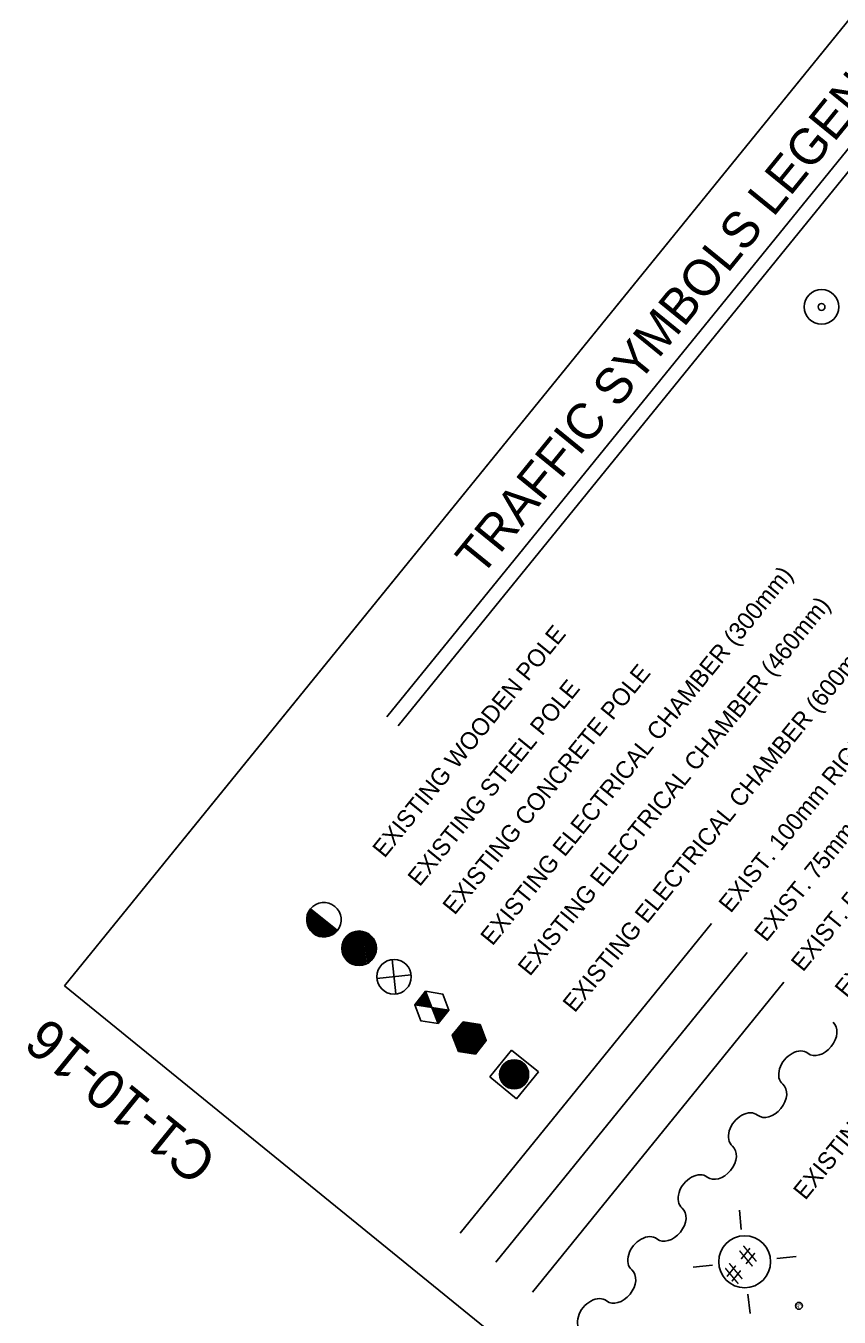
# Model space of a CAD drawing. Extents: x 592613 to 600223, y 4837996 to 4840103.
# Drawn here: x 592657.51 to 592677.9, y 4838962.54 to 4838994.9 of the extents above; entities that cross this region are included whole.
import ezdxf

# ---------------------------------------------------------------- set-up
doc = ezdxf.new("R2010")
doc.units = 0
for name, color, linetype in [('ENG_BORDER', 7, 'Continuous'), ('ENG_TX_BORDER', 7, 'Continuous'), ('TCS_100mm-EXIST', 7, 'Continuous'), ('TCS_50mm-EXIST', 7, 'Continuous'), ('TCS_75mm-EXIST', 7, 'Continuous'), ('TCS_ELEC-CHAMBER-EXIST', 7, 'Continuous'), ('TCS_LEGEND', 7, 'Continuous'), ('TCS_LUMINAIRE-EXIST', 7, 'Continuous'), ('TCS_POLE-EXIST', 7, 'Continuous'), ('TCS_POLE-NEW', 7, 'Continuous'), ('TCS_PUSHBUTTON', 7, 'Continuous'), ('TCS_SPAN-EXIST', 7, 'Continuous')]:
    doc.layers.add(name, color=color, linetype=linetype)

msp = doc.modelspace()

# ---------------------------------------------------------------- linework, layer by layer
at = {"layer": 'ENG_BORDER'}
for points in [[(592783.858, 4839125.156), (592658.479, 4838970.843)], [(592658.479, 4838970.843), (592762.862, 4838886.033)]]:
    msp.add_lwpolyline(points, dxfattribs=at)
at = {"layer": 'TCS_100mm-EXIST'}
msp.add_line((592668.401, 4838964.64), (592674.707, 4838972.401), dxfattribs=at)
at = {"layer": 'TCS_50mm-EXIST'}
msp.add_line((592670.214, 4838963.166), (592676.52, 4838970.928), dxfattribs=at)
at = {"layer": 'TCS_75mm-EXIST'}
msp.add_line((592669.292, 4838963.916), (592675.598, 4838971.677), dxfattribs=at)
at = {"layer": 'TCS_ELEC-CHAMBER-EXIST'}
for p, q in [((592667.302, 4838970.359), (592667.297, 4838970.408)), ((592667.316, 4838970.357), (592667.309, 4838970.424)), ((592667.331, 4838970.355), (592667.322, 4838970.44)), ((592667.346, 4838970.352), (592667.335, 4838970.456)), ((592667.361, 4838970.35), (592667.348, 4838970.472)), ((592667.375, 4838970.347), (592667.361, 4838970.488)), ((592667.39, 4838970.345), (592667.374, 4838970.504)), ((592667.405, 4838970.343), (592667.387, 4838970.519)), ((592667.42, 4838970.34), (592667.4, 4838970.535)), ((592667.435, 4838970.338), (592667.413, 4838970.551)), ((592667.449, 4838970.336), (592667.425, 4838970.567)), ((592667.464, 4838970.333), (592667.438, 4838970.583)), ((592667.479, 4838970.331), (592667.451, 4838970.599)), ((592667.494, 4838970.329), (592667.464, 4838970.615)), ((592667.509, 4838970.326), (592667.477, 4838970.63)), ((592667.523, 4838970.324), (592667.49, 4838970.646)), ((592667.538, 4838970.321), (592667.503, 4838970.662)), ((592667.553, 4838970.319), (592667.516, 4838970.678)), ((592667.568, 4838970.317), (592667.529, 4838970.694)), ((592667.582, 4838970.314), (592667.545, 4838970.677)), ((592667.597, 4838970.312), (592667.565, 4838970.625)), ((592667.612, 4838970.31), (592667.585, 4838970.573)), ((592667.627, 4838970.307), (592667.605, 4838970.521)), ((592667.642, 4838970.305), (592667.625, 4838970.469)), ((592667.656, 4838970.302), (592667.645, 4838970.416)), ((592667.272, 4838970.364), (592667.271, 4838970.377)), ((592667.287, 4838970.362), (592667.284, 4838970.392)), ((592667.671, 4838970.3), (592667.664, 4838970.364)), ((592667.686, 4838970.298), (592667.684, 4838970.312)), ((592667.708, 4838970.25), (592667.704, 4838970.295)), ((592667.728, 4838970.197), (592667.718, 4838970.293)), ((592667.748, 4838970.145), (592667.733, 4838970.29)), ((592667.768, 4838970.093), (592667.748, 4838970.288)), ((592667.788, 4838970.041), (592667.763, 4838970.285)), ((592667.808, 4838969.989), (592667.777, 4838970.283)), ((592667.828, 4838969.937), (592667.792, 4838970.281)), ((592667.847, 4838969.894), (592667.807, 4838970.278)), ((592667.86, 4838969.91), (592667.822, 4838970.276)), ((592667.873, 4838969.926), (592667.837, 4838970.274)), ((592667.885, 4838969.942), (592667.851, 4838970.271)), ((592667.898, 4838969.958), (592667.866, 4838970.269)), ((592667.911, 4838969.974), (592667.881, 4838970.267)), ((592667.924, 4838969.989), (592667.896, 4838970.264)), ((592667.937, 4838970.005), (592667.91, 4838970.262)), ((592667.95, 4838970.021), (592667.925, 4838970.259)), ((592667.963, 4838970.037), (592667.94, 4838970.257)), ((592667.976, 4838970.053), (592667.955, 4838970.255)), ((592667.989, 4838970.069), (592667.97, 4838970.252)), ((592668.001, 4838970.085), (592667.984, 4838970.25)), ((592668.014, 4838970.1), (592667.999, 4838970.248)), ((592668.027, 4838970.116), (592668.014, 4838970.245)), ((592668.04, 4838970.132), (592668.029, 4838970.243)), ((592668.053, 4838970.148), (592668.043, 4838970.241)), ((592668.066, 4838970.164), (592668.058, 4838970.238)), ((592668.079, 4838970.18), (592668.073, 4838970.236)), ((592668.092, 4838970.196), (592668.088, 4838970.233)), ((592668.105, 4838970.212), (592668.103, 4838970.231)), ((592668.117, 4838970.227), (592668.117, 4838970.229)), ((592668.2, 4838969.604), (592668.473, 4838969.94)), ((592668.473, 4838969.94), (592668.2, 4838969.604)), ((592668.473, 4838969.94), (592668.2, 4838969.604)), ((592668.473, 4838969.94), (592668.2, 4838969.604)), ((592668.397, 4838969.191), (592668.337, 4838969.773)), ((592668.412, 4838969.189), (592668.35, 4838969.788)), ((592668.427, 4838969.187), (592668.363, 4838969.804)), ((592668.442, 4838969.184), (592668.376, 4838969.82)), ((592668.456, 4838969.182), (592668.389, 4838969.836)), ((592668.471, 4838969.18), (592668.402, 4838969.852)), ((592668.486, 4838969.177), (592668.415, 4838969.868)), ((592668.501, 4838969.175), (592668.427, 4838969.884)), ((592668.516, 4838969.173), (592668.44, 4838969.9)), ((592668.53, 4838969.17), (592668.453, 4838969.915)), ((592668.545, 4838969.168), (592668.466, 4838969.931)), ((592668.473, 4838969.94), (592668.902, 4838969.872)), ((592668.902, 4838969.872), (592668.473, 4838969.94)), ((592668.902, 4838969.872), (592668.473, 4838969.94)), ((592668.902, 4838969.872), (592668.473, 4838969.94)), ((592668.56, 4838969.165), (592668.48, 4838969.939)), ((592668.575, 4838969.163), (592668.495, 4838969.937)), ((592668.589, 4838969.161), (592668.509, 4838969.934)), ((592668.604, 4838969.158), (592668.524, 4838969.932)), ((592668.619, 4838969.156), (592668.539, 4838969.93)), ((592668.634, 4838969.154), (592668.554, 4838969.927)), ((592668.649, 4838969.151), (592668.569, 4838969.925)), ((592668.663, 4838969.149), (592668.583, 4838969.923)), ((592668.678, 4838969.147), (592668.598, 4838969.92)), ((592668.693, 4838969.144), (592668.613, 4838969.918)), ((592668.708, 4838969.142), (592668.628, 4838969.915)), ((592668.722, 4838969.139), (592668.642, 4838969.913)), ((592668.737, 4838969.137), (592668.657, 4838969.911)), ((592668.752, 4838969.135), (592668.672, 4838969.908)), ((592668.767, 4838969.132), (592668.687, 4838969.906)), ((592668.782, 4838969.13), (592668.702, 4838969.904)), ((592668.795, 4838969.144), (592668.716, 4838969.901)), ((592668.808, 4838969.16), (592668.731, 4838969.899)), ((592668.82, 4838969.176), (592668.746, 4838969.897)), ((592668.833, 4838969.192), (592668.761, 4838969.894)), ((592668.846, 4838969.208), (592668.775, 4838969.892)), ((592668.859, 4838969.224), (592668.79, 4838969.889)), ((592668.872, 4838969.24), (592668.805, 4838969.887)), ((592668.885, 4838969.255), (592668.82, 4838969.885)), ((592668.898, 4838969.271), (592668.835, 4838969.882)), ((592668.911, 4838969.287), (592668.849, 4838969.88)), ((592668.924, 4838969.303), (592668.864, 4838969.878)), ((592668.936, 4838969.319), (592668.879, 4838969.875)), ((592668.949, 4838969.335), (592668.894, 4838969.873)), ((592668.902, 4838969.872), (592669.056, 4838969.466)), ((592669.056, 4838969.466), (592668.902, 4838969.872)), ((592669.056, 4838969.466), (592668.902, 4838969.872)), ((592669.056, 4838969.466), (592668.902, 4838969.872)), ((592668.962, 4838969.351), (592668.911, 4838969.847)), ((592668.975, 4838969.366), (592668.931, 4838969.795)), ((592668.2, 4838969.604), (592668.355, 4838969.198)), ((592668.2, 4838969.604), (592668.355, 4838969.198)), ((592668.2, 4838969.604), (592668.355, 4838969.198)), ((592668.2, 4838969.604), (592668.355, 4838969.198)), ((592668.213, 4838969.569), (592668.208, 4838969.614)), ((592668.233, 4838969.517), (592668.221, 4838969.63)), ((592668.253, 4838969.465), (592668.234, 4838969.646)), ((592668.273, 4838969.413), (592668.247, 4838969.662)), ((592668.293, 4838969.36), (592668.26, 4838969.677)), ((592668.313, 4838969.308), (592668.273, 4838969.693)), ((592668.333, 4838969.256), (592668.286, 4838969.709)), ((592668.352, 4838969.204), (592668.299, 4838969.725)), ((592668.368, 4838969.196), (592668.311, 4838969.741)), ((592668.383, 4838969.194), (592668.324, 4838969.757)), ((592668.783, 4838969.13), (592669.056, 4838969.466)), ((592668.783, 4838969.13), (592669.056, 4838969.466)), ((592668.783, 4838969.13), (592669.056, 4838969.466)), ((592668.783, 4838969.13), (592669.056, 4838969.466)), ((592668.988, 4838969.382), (592668.951, 4838969.743)), ((592669.001, 4838969.398), (592668.971, 4838969.691)), ((592669.014, 4838969.414), (592668.991, 4838969.638)), ((592669.027, 4838969.43), (592669.011, 4838969.586)), ((592669.04, 4838969.446), (592669.031, 4838969.534)), ((592669.053, 4838969.462), (592669.05, 4838969.482)), ((592668.355, 4838969.198), (592668.783, 4838969.13)), ((592668.355, 4838969.198), (592668.783, 4838969.13)), ((592668.355, 4838969.198), (592668.783, 4838969.13)), ((592668.355, 4838969.198), (592668.783, 4838969.13)), ((592669.143, 4838968.557), (592669.69, 4838969.231)), ((592669.69, 4838969.231), (592670.364, 4838968.684)), ((592669.475, 4838968.386), (592669.433, 4838968.793)), ((592669.483, 4838968.377), (592669.439, 4838968.804)), ((592669.492, 4838968.368), (592669.445, 4838968.814)), ((592669.5, 4838968.36), (592669.452, 4838968.824)), ((592669.508, 4838968.352), (592669.458, 4838968.833)), ((592669.516, 4838968.345), (592669.464, 4838968.842)), ((592669.524, 4838968.338), (592669.471, 4838968.85)), ((592669.532, 4838968.332), (592669.477, 4838968.857)), ((592669.539, 4838968.326), (592669.484, 4838968.865)), ((592669.547, 4838968.321), (592669.49, 4838968.872)), ((592669.555, 4838968.315), (592669.497, 4838968.879)), ((592669.563, 4838968.31), (592669.503, 4838968.885)), ((592669.571, 4838968.306), (592669.51, 4838968.891)), ((592669.578, 4838968.301), (592669.517, 4838968.897)), ((592669.586, 4838968.297), (592669.523, 4838968.903)), ((592669.594, 4838968.293), (592669.53, 4838968.908)), ((592669.601, 4838968.29), (592669.537, 4838968.913)), ((592669.609, 4838968.286), (592669.544, 4838968.918)), ((592669.617, 4838968.283), (592669.55, 4838968.923)), ((592669.624, 4838968.28), (592669.557, 4838968.927)), ((592669.632, 4838968.277), (592669.564, 4838968.931)), ((592669.639, 4838968.275), (592669.571, 4838968.935)), ((592669.647, 4838968.272), (592669.578, 4838968.939)), ((592669.654, 4838968.27), (592669.585, 4838968.943)), ((592669.662, 4838968.268), (592669.592, 4838968.947)), ((592669.669, 4838968.266), (592669.598, 4838968.95)), ((592669.677, 4838968.265), (592669.605, 4838968.953)), ((592669.684, 4838968.263), (592669.612, 4838968.956)), ((592669.691, 4838968.262), (592669.619, 4838968.959)), ((592669.699, 4838968.261), (592669.626, 4838968.962)), ((592669.706, 4838968.259), (592669.633, 4838968.964)), ((592669.714, 4838968.259), (592669.64, 4838968.967)), ((592669.721, 4838968.258), (592669.647, 4838968.969)), ((592669.728, 4838968.257), (592669.654, 4838968.971)), ((592669.736, 4838968.257), (592669.661, 4838968.973)), ((592669.743, 4838968.257), (592669.669, 4838968.975)), ((592669.75, 4838968.256), (592669.676, 4838968.976)), ((592669.757, 4838968.256), (592669.683, 4838968.978)), ((592669.765, 4838968.257), (592669.69, 4838968.979)), ((592669.772, 4838968.257), (592669.697, 4838968.98)), ((592669.779, 4838968.257), (592669.704, 4838968.981)), ((592669.786, 4838968.258), (592669.711, 4838968.982)), ((592669.794, 4838968.259), (592669.719, 4838968.983)), ((592669.801, 4838968.259), (592669.726, 4838968.984)), ((592669.808, 4838968.26), (592669.733, 4838968.984)), ((592669.815, 4838968.262), (592669.74, 4838968.984)), ((592669.822, 4838968.263), (592669.747, 4838968.985)), ((592669.829, 4838968.264), (592669.755, 4838968.985)), ((592669.836, 4838968.266), (592669.762, 4838968.985)), ((592669.843, 4838968.268), (592669.769, 4838968.984)), ((592669.851, 4838968.269), (592669.777, 4838968.984)), ((592669.858, 4838968.272), (592669.784, 4838968.983)), ((592669.865, 4838968.274), (592669.791, 4838968.983)), ((592669.872, 4838968.276), (592669.799, 4838968.982)), ((592669.879, 4838968.278), (592669.806, 4838968.981)), ((592669.886, 4838968.281), (592669.813, 4838968.98)), ((592669.893, 4838968.284), (592669.821, 4838968.978)), ((592669.9, 4838968.287), (592669.828, 4838968.977)), ((592669.907, 4838968.29), (592669.836, 4838968.975)), ((592669.913, 4838968.293), (592669.843, 4838968.974)), ((592669.92, 4838968.297), (592669.851, 4838968.972)), ((592669.927, 4838968.3), (592669.858, 4838968.969)), ((592669.934, 4838968.304), (592669.866, 4838968.967)), ((592669.941, 4838968.308), (592669.873, 4838968.965)), ((592669.948, 4838968.312), (592669.881, 4838968.962)), ((592669.955, 4838968.317), (592669.888, 4838968.959)), ((592669.961, 4838968.321), (592669.896, 4838968.956)), ((592669.968, 4838968.326), (592669.903, 4838968.952)), ((592669.975, 4838968.331), (592669.911, 4838968.949)), ((592669.982, 4838968.337), (592669.919, 4838968.945)), ((592669.988, 4838968.342), (592669.926, 4838968.941)), ((592669.995, 4838968.348), (592669.934, 4838968.937)), ((592670.002, 4838968.354), (592669.942, 4838968.932)), ((592670.008, 4838968.36), (592669.95, 4838968.927)), ((592670.015, 4838968.367), (592669.957, 4838968.922)), ((592670.021, 4838968.374), (592669.965, 4838968.917)), ((592670.028, 4838968.381), (592669.973, 4838968.911)), ((592670.034, 4838968.389), (592669.981, 4838968.905)), ((592670.041, 4838968.397), (592669.989, 4838968.899)), ((592670.047, 4838968.405), (592669.997, 4838968.892)), ((592670.054, 4838968.414), (592670.005, 4838968.884)), ((592670.06, 4838968.423), (592670.013, 4838968.876)), ((592670.066, 4838968.433), (592670.021, 4838968.868)), ((592670.072, 4838968.444), (592670.029, 4838968.858)), ((592670.078, 4838968.456), (592670.038, 4838968.848)), ((592670.084, 4838968.468), (592670.046, 4838968.838)), ((592670.09, 4838968.481), (592670.055, 4838968.826)), ((592670.096, 4838968.496), (592670.063, 4838968.812)), ((592670.102, 4838968.513), (592670.072, 4838968.797)), ((592669.817, 4838968.01), (592669.143, 4838968.557)), ((592669.403, 4838968.523), (592669.39, 4838968.644)), ((592669.413, 4838968.491), (592669.394, 4838968.678)), ((592669.423, 4838968.468), (592669.399, 4838968.702)), ((592669.432, 4838968.45), (592669.404, 4838968.722)), ((592669.441, 4838968.434), (592669.409, 4838968.739)), ((592669.45, 4838968.42), (592669.415, 4838968.755)), ((592669.458, 4838968.408), (592669.421, 4838968.769)), ((592669.467, 4838968.396), (592669.427, 4838968.781)), ((592670.364, 4838968.684), (592669.817, 4838968.01)), ((592670.107, 4838968.532), (592670.081, 4838968.78)), ((592670.112, 4838968.554), (592670.091, 4838968.759)), ((592670.116, 4838968.584), (592670.101, 4838968.731)), ((592670.117, 4838968.638), (592670.113, 4838968.678))]:
    msp.add_line(p, q, dxfattribs=at)
for points in [[(592667.535, 4838970.702), (592667.69, 4838970.297), (592667.262, 4838970.366)], [(592667.845, 4838969.892), (592667.69, 4838970.297), (592668.118, 4838970.229)]]:
    msp.add_lwpolyline(points, close=True, dxfattribs=at)
for points in [[(592668.118, 4838970.229), (592667.964, 4838970.634), (592667.535, 4838970.702)], [(592667.262, 4838970.366), (592667.417, 4838969.96), (592667.845, 4838969.892)]]:
    msp.add_lwpolyline(points, dxfattribs=at)
msp.add_circle((592669.754, 4838968.621), 0.364, dxfattribs=at)
at = {"layer": 'TCS_LEGEND'}
for p, q in [((592666.56, 4838977.581), (592681.077, 4838995.448)), ((592666.842, 4838977.353), (592681.359, 4838995.22))]:
    msp.add_line(p, q, dxfattribs=at)
msp.add_lwpolyline([(592661.217, 4838974.213), (592683.281, 4839001.368)], dxfattribs=at)
at = {"layer": 'TCS_LUMINAIRE-EXIST'}
for p, q in [((592675.451, 4838964.733), (592675.401, 4838965.219)), ((592676.343, 4838964.008), (592676.829, 4838964.059)), ((592674.726, 4838963.841), (592674.24, 4838963.791)), ((592675.618, 4838963.116), (592675.669, 4838962.63))]:
    msp.add_line(p, q, dxfattribs=at)
msp.add_circle((592675.535, 4838963.925), 0.651, dxfattribs=at)
at = {"layer": 'TCS_POLE-EXIST'}
for p, q in [((592664.644, 4838972.228), (592664.596, 4838972.69)), ((592664.661, 4838972.208), (592664.609, 4838972.713)), ((592664.677, 4838972.191), (592664.621, 4838972.733)), ((592664.693, 4838972.176), (592664.634, 4838972.752)), ((592664.709, 4838972.162), (592664.646, 4838972.769)), ((592664.648, 4838972.77), (592665.321, 4838972.223)), ((592664.648, 4838972.77), (592664.648, 4838972.77)), ((592664.725, 4838972.149), (592664.662, 4838972.759)), ((592664.741, 4838972.138), (592664.678, 4838972.746)), ((592664.756, 4838972.128), (592664.694, 4838972.733)), ((592664.772, 4838972.119), (592664.71, 4838972.72)), ((592664.787, 4838972.111), (592664.725, 4838972.707)), ((592664.802, 4838972.103), (592664.741, 4838972.694)), ((592664.818, 4838972.096), (592664.757, 4838972.681)), ((592664.572, 4838972.362), (592664.553, 4838972.544)), ((592664.592, 4838972.313), (592664.562, 4838972.597)), ((592664.61, 4838972.278), (592664.573, 4838972.634)), ((592664.627, 4838972.251), (592664.584, 4838972.664)), ((592664.833, 4838972.091), (592664.773, 4838972.668)), ((592664.848, 4838972.085), (592664.789, 4838972.656)), ((592664.863, 4838972.081), (592664.805, 4838972.643)), ((592664.878, 4838972.076), (592664.821, 4838972.63)), ((592664.893, 4838972.073), (592664.836, 4838972.617)), ((592664.908, 4838972.07), (592664.852, 4838972.604)), ((592664.922, 4838972.068), (592664.868, 4838972.591)), ((592664.937, 4838972.066), (592664.884, 4838972.578)), ((592664.952, 4838972.064), (592664.9, 4838972.565)), ((592664.966, 4838972.063), (592664.916, 4838972.552)), ((592664.981, 4838972.063), (592664.932, 4838972.54)), ((592664.996, 4838972.063), (592664.948, 4838972.527)), ((592665.01, 4838972.064), (592664.963, 4838972.514)), ((592665.024, 4838972.065), (592664.979, 4838972.501)), ((592665.039, 4838972.067), (592664.995, 4838972.488)), ((592665.053, 4838972.069), (592665.011, 4838972.475)), ((592665.067, 4838972.071), (592665.027, 4838972.462)), ((592665.082, 4838972.074), (592665.043, 4838972.449)), ((592665.096, 4838972.078), (592665.059, 4838972.436)), ((592665.11, 4838972.082), (592665.075, 4838972.423)), ((592665.124, 4838972.086), (592665.09, 4838972.411)), ((592665.138, 4838972.091), (592665.106, 4838972.398)), ((592665.152, 4838972.097), (592665.122, 4838972.385)), ((592665.166, 4838972.103), (592665.138, 4838972.372)), ((592665.18, 4838972.11), (592665.154, 4838972.359)), ((592665.193, 4838972.117), (592665.17, 4838972.346)), ((592665.207, 4838972.125), (592665.186, 4838972.333)), ((592665.221, 4838972.133), (592665.201, 4838972.32)), ((592665.234, 4838972.142), (592665.217, 4838972.307)), ((592665.248, 4838972.152), (592665.233, 4838972.295)), ((592665.261, 4838972.163), (592665.249, 4838972.282)), ((592665.275, 4838972.174), (592665.265, 4838972.269)), ((592665.288, 4838972.187), (592665.281, 4838972.256)), ((592665.301, 4838972.2), (592665.297, 4838972.243)), ((592665.314, 4838972.215), (592665.313, 4838972.23)), ((592665.32, 4838972.222), (592665.32, 4838972.224)), ((592665.596, 4838971.44), (592665.532, 4838972.058)), ((592665.635, 4838971.412), (592665.565, 4838972.093)), ((592665.674, 4838971.391), (592665.598, 4838972.122)), ((592665.712, 4838971.374), (592665.632, 4838972.146)), ((592665.75, 4838971.362), (592665.666, 4838972.166)), ((592665.787, 4838971.353), (592665.701, 4838972.181)), ((592665.824, 4838971.348), (592665.736, 4838972.194)), ((592665.86, 4838971.346), (592665.772, 4838972.203)), ((592665.896, 4838971.347), (592665.807, 4838972.21)), ((592665.932, 4838971.351), (592665.843, 4838972.213)), ((592665.968, 4838971.359), (592665.88, 4838972.213)), ((592666.003, 4838971.369), (592665.916, 4838972.211)), ((592666.038, 4838971.382), (592665.953, 4838972.205)), ((592666.073, 4838971.399), (592665.99, 4838972.195)), ((592666.107, 4838971.42), (592666.028, 4838972.182)), ((592666.141, 4838971.445), (592666.066, 4838972.164)), ((592666.174, 4838971.475), (592666.105, 4838972.141)), ((592666.206, 4838971.512), (592666.144, 4838972.112)), ((592666.238, 4838971.558), (592666.185, 4838972.073)), ((592665.471, 4838971.599), (592665.442, 4838971.876)), ((592665.515, 4838971.524), (592665.47, 4838971.959)), ((592665.556, 4838971.475), (592665.5, 4838972.015)), ((592666.268, 4838971.619), (592666.227, 4838972.019)), ((592666.294, 4838971.717), (592666.272, 4838971.929)), ((592666.786, 4838970.636), (592666.697, 4838971.499)), ((592666.31, 4838971.023), (592667.173, 4838971.112))]:
    msp.add_line(p, q, dxfattribs=at)
for centre in [(592665.865, 4838971.78), (592666.742, 4838971.068)]:
    msp.add_circle(centre, 0.434, dxfattribs=at)
for centre, start, end in [((592664.985, 4838972.497), 140.9061, 320.9061), ((592664.983, 4838972.495), 320.9061, 140.9061)]:
    msp.add_arc(centre, 0.434, start, end, dxfattribs=at)
at = {"layer": 'TCS_POLE-NEW'}
for radius in [0.434, 0.0867]:
    msp.add_circle((592677.462, 4838987.853), radius, dxfattribs=at)
at = {"layer": 'TCS_PUSHBUTTON'}
msp.add_circle((592676.894, 4838962.821), 0.0867, dxfattribs=at)
at = {"layer": 'TCS_SPAN-EXIST'}
for centre, start_param, end_param in [((592677.435, 4838969.539), 3.141593, 6.283185), ((592676.804, 4838968.763), 0, 3.141593), ((592676.173, 4838967.987), 3.141593, 6.283185), ((592675.542, 4838967.212), 6.283185, 9.424778), ((592674.911, 4838966.436), 3.141593, 6.283185), ((592674.281, 4838965.66), 6.283185, 9.424778), ((592673.65, 4838964.884), 3.141593, 6.283185), ((592673.019, 4838964.108), 0, 3.141593), ((592672.388, 4838963.332), 3.141593, 6.283185), ((592671.757, 4838962.556), 0, 3.141593)]:
    msp.add_ellipse(centre, major_axis=(0.315, 0.388), ratio=0.7, start_param=start_param, end_param=end_param, dxfattribs=at)

# ---------------------------------------------------------------- texts
at = {"layer": 'ENG_TX_BORDER'}
msp.add_text('C1-10-16', height=1, rotation=140.906, dxfattribs=at).set_placement((592662.368, 4838966.571))
at = {"layer": 'TCS_LEGEND'}
for s, height, p in [('TRAFFIC SYMBOLS LEGEND', 0.90363, (592668.925, 4838981.067)), ('EXISTING ELECTRICAL CHAMBER (300mm)', 0.43374, (592669.21, 4838971.823)), ('EXISTING ELECTRICAL CHAMBER (460mm)', 0.43374, (592670.148, 4838971.061)), ('EXISTING WOODEN POLE', 0.43374, (592666.503, 4838974.022)), ('EXISTING ELECTRICAL CHAMBER (600mm)', 0.43374, (592671.273, 4838970.147)), ('EXISTING CONCRETE POLE', 0.43374, (592668.261, 4838972.594)), ('EXISTING STEEL POLE', 0.43374, (592667.385, 4838973.306)), ('EXIST. 100mm RIGID PVC', 0.43374, (592675.183, 4838972.643)), ('EXIST. 75mm RIGID PVC', 0.43374, (592676.074, 4838971.919)), ('EXISTING O/H CABLE TRAFFIC', 0.43374, (592678.094, 4838970.519)), ('EXIST. 50mm RIGID PVC', 0.43374, (592676.997, 4838971.17)), ('EXISTING LUMINAIRE', 0.43374, (592677.055, 4838965.449))]:
    msp.add_text(s, height=height, rotation=50.9061, dxfattribs=at).set_placement(p)
at = {"layer": 'TCS_LUMINAIRE-EXIST'}
msp.add_text('# #', height=0.506, rotation=50.9061, dxfattribs=at).set_placement((592675.339, 4838963.326))
at = {"layer": 'TCS_PUSHBUTTON'}
msp.add_text('PB', height=0.0906, rotation=50.9061, dxfattribs=at).set_placement((592676.893, 4838962.755))

doc.saveas('drawing.dxf')
